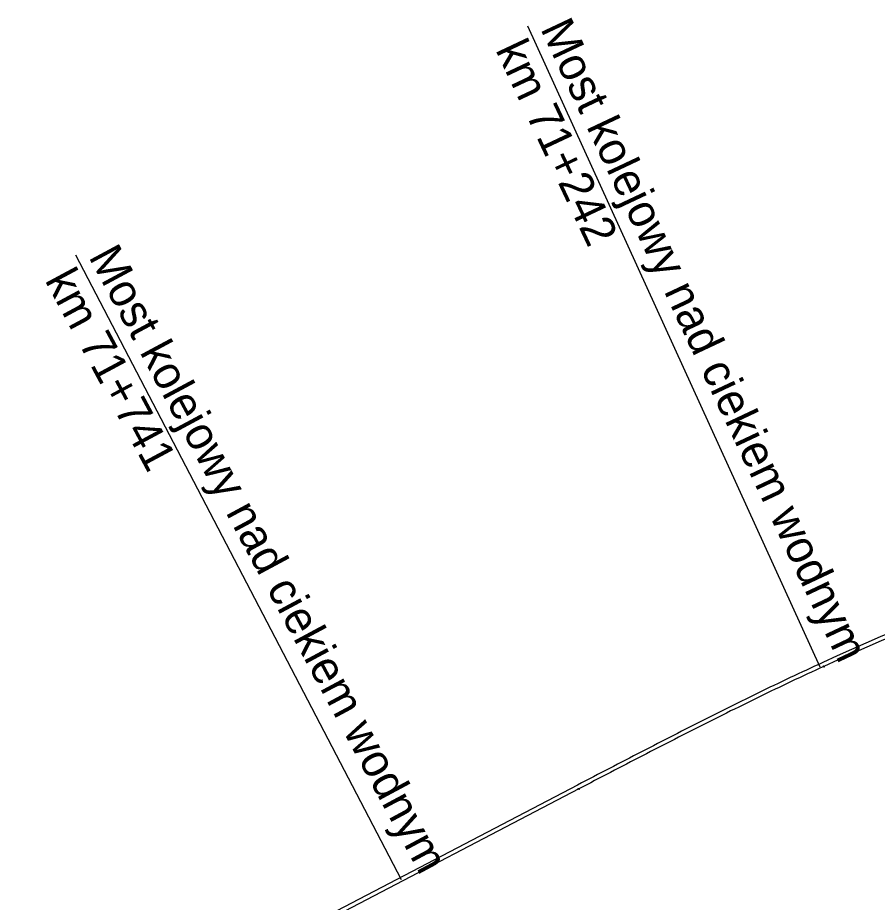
# Model space of a CAD drawing. Extents: x 6540591 to 6566579, y 5525343 to 5532423.
# Drawn here: x 6547196 to 6548106, y 5526559 to 5527495 of the extents above; entities that cross this region are included whole.
import ezdxf

# ---------------------------------------------------------------- set-up
doc = ezdxf.new("R2010")
doc.units = 0
for name, color, linetype in [('IR_ps_geometria', 7, 'Continuous'), ('TOR_PS_OPIS_T-opisy dodatkowe', 7, 'Continuous'), ('TOR_PS_T-tory projektowane', 7, 'Continuous')]:
    doc.layers.add(name, color=color, linetype=linetype)

msp = doc.modelspace()

# ---------------------------------------------------------------- linework, layer by layer
at = {"layer": 'IR_ps_geometria'}
for points in [[(6548049.46, 5526808.53), (6548049.56, 5526808.3), (6548049.59, 5526808.31), (6548049.62, 5526808.32), (6548049.66, 5526808.32), (6548049.69, 5526808.32), (6548049.72, 5526808.32), (6548049.75, 5526808.31), (6548049.78, 5526808.29), (6548049.81, 5526808.28), (6548049.84, 5526808.26), (6548049.86, 5526808.23), (6548049.88, 5526808.2), (6548049.89, 5526808.18), (6548049.9, 5526808.15), (6548049.91, 5526808.11), (6548049.91, 5526808.08), (6548049.91, 5526808.05), (6548049.91, 5526808.02), (6548049.9, 5526807.98), (6548049.89, 5526807.95), (6548049.87, 5526807.93), (6548049.85, 5526807.9), (6548049.82, 5526807.88), (6548049.8, 5526807.86), (6548049.77, 5526807.84), (6548049.74, 5526807.83), (6548049.71, 5526807.83), (6548049.67, 5526807.82), (6548049.64, 5526807.82), (6548049.61, 5526807.83), (6548049.58, 5526807.84), (6548049.55, 5526807.85), (6548049.52, 5526807.87), (6548049.49, 5526807.89), (6548049.47, 5526807.91), (6548049.45, 5526807.94), (6548049.44, 5526807.97), (6548049.43, 5526808), (6548049.42, 5526808.03), (6548049.42, 5526808.06), (6548049.42, 5526808.1), (6548049.42, 5526808.13), (6548049.43, 5526808.16), (6548049.44, 5526808.19), (6548049.46, 5526808.22), (6548049.48, 5526808.24), (6548049.51, 5526808.26), (6548049.53, 5526808.28), (6548049.56, 5526808.3), (6548049.35, 5526808.75), (6548049.32, 5526808.74), (6548049.29, 5526808.74), (6548049.26, 5526808.73), (6548049.23, 5526808.73), (6548049.19, 5526808.74), (6548049.16, 5526808.75), (6548049.13, 5526808.76), (6548049.1, 5526808.78), (6548049.08, 5526808.8), (6548049.06, 5526808.82), (6548049.04, 5526808.85), (6548049.02, 5526808.88), (6548049.01, 5526808.91), (6548049, 5526808.94), (6548049, 5526808.97), (6548049, 5526809.01), (6548049.01, 5526809.04), (6548049.01, 5526809.07), (6548049.03, 5526809.1), (6548049.05, 5526809.13), (6548049.07, 5526809.15), (6548049.09, 5526809.17), (6548049.12, 5526809.19), (6548049.15, 5526809.21), (6548049.18, 5526809.22), (6548049.21, 5526809.23), (6548049.24, 5526809.23), (6548049.27, 5526809.23), (6548049.31, 5526809.23), (6548049.34, 5526809.22), (6548049.37, 5526809.2), (6548049.39, 5526809.19), (6548049.42, 5526809.16), (6548049.44, 5526809.14), (6548049.46, 5526809.11), (6548049.48, 5526809.09), (6548049.49, 5526809.05), (6548049.5, 5526809.02), (6548049.5, 5526808.99), (6548049.5, 5526808.96), (6548049.49, 5526808.93), (6548049.48, 5526808.89), (6548049.47, 5526808.86), (6548049.45, 5526808.84), (6548049.43, 5526808.81), (6548049.41, 5526808.79), (6548049.38, 5526808.77), (6548049.35, 5526808.75)], [(6548049.46, 5526808.53), (6548049.56, 5526808.3), (6548049.59, 5526808.31), (6548049.62, 5526808.32), (6548049.66, 5526808.32), (6548049.69, 5526808.32), (6548049.72, 5526808.32), (6548049.75, 5526808.31), (6548049.78, 5526808.29), (6548049.81, 5526808.28), (6548049.84, 5526808.26), (6548049.86, 5526808.23), (6548049.88, 5526808.2), (6548049.89, 5526808.18), (6548049.9, 5526808.15), (6548049.91, 5526808.11), (6548049.91, 5526808.08), (6548049.91, 5526808.05), (6548049.91, 5526808.02), (6548049.9, 5526807.98), (6548049.89, 5526807.95), (6548049.87, 5526807.93), (6548049.85, 5526807.9), (6548049.82, 5526807.88), (6548049.8, 5526807.86), (6548049.77, 5526807.84), (6548049.74, 5526807.83), (6548049.71, 5526807.83), (6548049.67, 5526807.82), (6548049.64, 5526807.82), (6548049.61, 5526807.83), (6548049.58, 5526807.84), (6548049.55, 5526807.85), (6548049.52, 5526807.87), (6548049.49, 5526807.89), (6548049.47, 5526807.91), (6548049.45, 5526807.94), (6548049.44, 5526807.97), (6548049.43, 5526808), (6548049.42, 5526808.03), (6548049.42, 5526808.06), (6548049.42, 5526808.1), (6548049.42, 5526808.13), (6548049.43, 5526808.16), (6548049.44, 5526808.19), (6548049.46, 5526808.22), (6548049.48, 5526808.24), (6548049.51, 5526808.26), (6548049.53, 5526808.28), (6548049.56, 5526808.3), (6548049.35, 5526808.75), (6548049.32, 5526808.74), (6548049.29, 5526808.74), (6548049.26, 5526808.73), (6548049.23, 5526808.73), (6548049.19, 5526808.74), (6548049.16, 5526808.75), (6548049.13, 5526808.76), (6548049.1, 5526808.78), (6548049.08, 5526808.8), (6548049.06, 5526808.82), (6548049.04, 5526808.85), (6548049.02, 5526808.88), (6548049.01, 5526808.91), (6548049, 5526808.94), (6548049, 5526808.97), (6548049, 5526809.01), (6548049.01, 5526809.04), (6548049.01, 5526809.07), (6548049.03, 5526809.1), (6548049.05, 5526809.13), (6548049.07, 5526809.15), (6548049.09, 5526809.17), (6548049.12, 5526809.19), (6548049.15, 5526809.21), (6548049.18, 5526809.22), (6548049.21, 5526809.23), (6548049.24, 5526809.23), (6548049.27, 5526809.23), (6548049.31, 5526809.23), (6548049.34, 5526809.22), (6548049.37, 5526809.2), (6548049.39, 5526809.19), (6548049.42, 5526809.16), (6548049.44, 5526809.14), (6548049.46, 5526809.11), (6548049.48, 5526809.09), (6548049.49, 5526809.05), (6548049.5, 5526809.02), (6548049.5, 5526808.99), (6548049.5, 5526808.96), (6548049.49, 5526808.93), (6548049.48, 5526808.89), (6548049.47, 5526808.86), (6548049.45, 5526808.84), (6548049.43, 5526808.81), (6548049.41, 5526808.79), (6548049.38, 5526808.77), (6548049.35, 5526808.75)], [(6548049.46, 5526808.53), (6548049.56, 5526808.3), (6548049.59, 5526808.31), (6548049.62, 5526808.32), (6548049.66, 5526808.32), (6548049.69, 5526808.32), (6548049.72, 5526808.32), (6548049.75, 5526808.31), (6548049.78, 5526808.29), (6548049.81, 5526808.28), (6548049.84, 5526808.26), (6548049.86, 5526808.23), (6548049.88, 5526808.2), (6548049.89, 5526808.18), (6548049.9, 5526808.15), (6548049.91, 5526808.11), (6548049.91, 5526808.08), (6548049.91, 5526808.05), (6548049.91, 5526808.02), (6548049.9, 5526807.98), (6548049.89, 5526807.95), (6548049.87, 5526807.93), (6548049.85, 5526807.9), (6548049.82, 5526807.88), (6548049.8, 5526807.86), (6548049.77, 5526807.84), (6548049.74, 5526807.83), (6548049.71, 5526807.83), (6548049.67, 5526807.82), (6548049.64, 5526807.82), (6548049.61, 5526807.83), (6548049.58, 5526807.84), (6548049.55, 5526807.85), (6548049.52, 5526807.87), (6548049.49, 5526807.89), (6548049.47, 5526807.91), (6548049.45, 5526807.94), (6548049.44, 5526807.97), (6548049.43, 5526808), (6548049.42, 5526808.03), (6548049.42, 5526808.06), (6548049.42, 5526808.1), (6548049.42, 5526808.13), (6548049.43, 5526808.16), (6548049.44, 5526808.19), (6548049.46, 5526808.22), (6548049.48, 5526808.24), (6548049.51, 5526808.26), (6548049.53, 5526808.28), (6548049.56, 5526808.3), (6548049.35, 5526808.75), (6548049.32, 5526808.74), (6548049.29, 5526808.74), (6548049.26, 5526808.73), (6548049.23, 5526808.73), (6548049.19, 5526808.74), (6548049.16, 5526808.75), (6548049.13, 5526808.76), (6548049.1, 5526808.78), (6548049.08, 5526808.8), (6548049.06, 5526808.82), (6548049.04, 5526808.85), (6548049.02, 5526808.88), (6548049.01, 5526808.91), (6548049, 5526808.94), (6548049, 5526808.97), (6548049, 5526809.01), (6548049.01, 5526809.04), (6548049.01, 5526809.07), (6548049.03, 5526809.1), (6548049.05, 5526809.13), (6548049.07, 5526809.15), (6548049.09, 5526809.17), (6548049.12, 5526809.19), (6548049.15, 5526809.21), (6548049.18, 5526809.22), (6548049.21, 5526809.23), (6548049.24, 5526809.23), (6548049.27, 5526809.23), (6548049.31, 5526809.23), (6548049.34, 5526809.22), (6548049.37, 5526809.2), (6548049.39, 5526809.19), (6548049.42, 5526809.16), (6548049.44, 5526809.14), (6548049.46, 5526809.11), (6548049.48, 5526809.09), (6548049.49, 5526809.05), (6548049.5, 5526809.02), (6548049.5, 5526808.99), (6548049.5, 5526808.96), (6548049.49, 5526808.93), (6548049.48, 5526808.89), (6548049.47, 5526808.86), (6548049.45, 5526808.84), (6548049.43, 5526808.81), (6548049.41, 5526808.79), (6548049.38, 5526808.77), (6548049.35, 5526808.75)], [(6548049.46, 5526808.53), (6548049.56, 5526808.3), (6548049.59, 5526808.31), (6548049.62, 5526808.32), (6548049.66, 5526808.32), (6548049.69, 5526808.32), (6548049.72, 5526808.32), (6548049.75, 5526808.31), (6548049.78, 5526808.29), (6548049.81, 5526808.28), (6548049.84, 5526808.26), (6548049.86, 5526808.23), (6548049.88, 5526808.2), (6548049.89, 5526808.18), (6548049.9, 5526808.15), (6548049.91, 5526808.11), (6548049.91, 5526808.08), (6548049.91, 5526808.05), (6548049.91, 5526808.02), (6548049.9, 5526807.98), (6548049.89, 5526807.95), (6548049.87, 5526807.93), (6548049.85, 5526807.9), (6548049.82, 5526807.88), (6548049.8, 5526807.86), (6548049.77, 5526807.84), (6548049.74, 5526807.83), (6548049.71, 5526807.83), (6548049.67, 5526807.82), (6548049.64, 5526807.82), (6548049.61, 5526807.83), (6548049.58, 5526807.84), (6548049.55, 5526807.85), (6548049.52, 5526807.87), (6548049.49, 5526807.89), (6548049.47, 5526807.91), (6548049.45, 5526807.94), (6548049.44, 5526807.97), (6548049.43, 5526808), (6548049.42, 5526808.03), (6548049.42, 5526808.06), (6548049.42, 5526808.1), (6548049.42, 5526808.13), (6548049.43, 5526808.16), (6548049.44, 5526808.19), (6548049.46, 5526808.22), (6548049.48, 5526808.24), (6548049.51, 5526808.26), (6548049.53, 5526808.28), (6548049.56, 5526808.3), (6548049.35, 5526808.75), (6548049.32, 5526808.74), (6548049.29, 5526808.74), (6548049.26, 5526808.73), (6548049.23, 5526808.73), (6548049.19, 5526808.74), (6548049.16, 5526808.75), (6548049.13, 5526808.76), (6548049.1, 5526808.78), (6548049.08, 5526808.8), (6548049.06, 5526808.82), (6548049.04, 5526808.85), (6548049.02, 5526808.88), (6548049.01, 5526808.91), (6548049, 5526808.94), (6548049, 5526808.97), (6548049, 5526809.01), (6548049.01, 5526809.04), (6548049.01, 5526809.07), (6548049.03, 5526809.1), (6548049.05, 5526809.13), (6548049.07, 5526809.15), (6548049.09, 5526809.17), (6548049.12, 5526809.19), (6548049.15, 5526809.21), (6548049.18, 5526809.22), (6548049.21, 5526809.23), (6548049.24, 5526809.23), (6548049.27, 5526809.23), (6548049.31, 5526809.23), (6548049.34, 5526809.22), (6548049.37, 5526809.2), (6548049.39, 5526809.19), (6548049.42, 5526809.16), (6548049.44, 5526809.14), (6548049.46, 5526809.11), (6548049.48, 5526809.09), (6548049.49, 5526809.05), (6548049.5, 5526809.02), (6548049.5, 5526808.99), (6548049.5, 5526808.96), (6548049.49, 5526808.93), (6548049.48, 5526808.89), (6548049.47, 5526808.86), (6548049.45, 5526808.84), (6548049.43, 5526808.81), (6548049.41, 5526808.79), (6548049.38, 5526808.77), (6548049.35, 5526808.75)], [(6547790.06, 5526678.94), (6547790.17, 5526678.72), (6547790.2, 5526678.73), (6547790.24, 5526678.74), (6547790.27, 5526678.75), (6547790.3, 5526678.75), (6547790.33, 5526678.74), (6547790.37, 5526678.74), (6547790.4, 5526678.72), (6547790.42, 5526678.71), (6547790.45, 5526678.69), (6547790.47, 5526678.67), (6547790.5, 5526678.64), (6547790.51, 5526678.61), (6547790.53, 5526678.58), (6547790.53, 5526678.55), (6547790.54, 5526678.52), (6547790.54, 5526678.49), (6547790.54, 5526678.45), (6547790.53, 5526678.42), (6547790.52, 5526678.39), (6547790.5, 5526678.36), (6547790.48, 5526678.34), (6547790.46, 5526678.31), (6547790.43, 5526678.29), (6547790.41, 5526678.28), (6547790.38, 5526678.26), (6547790.34, 5526678.25), (6547790.31, 5526678.25), (6547790.28, 5526678.25), (6547790.25, 5526678.25), (6547790.22, 5526678.26), (6547790.18, 5526678.27), (6547790.16, 5526678.29), (6547790.13, 5526678.31), (6547790.11, 5526678.33), (6547790.09, 5526678.35), (6547790.07, 5526678.38), (6547790.06, 5526678.41), (6547790.05, 5526678.44), (6547790.04, 5526678.47), (6547790.04, 5526678.51), (6547790.04, 5526678.54), (6547790.05, 5526678.57), (6547790.06, 5526678.6), (6547790.08, 5526678.63), (6547790.1, 5526678.66), (6547790.12, 5526678.68), (6547790.15, 5526678.7), (6547790.17, 5526678.72), (6547789.94, 5526679.16), (6547789.91, 5526679.15), (6547789.88, 5526679.14), (6547789.85, 5526679.13), (6547789.82, 5526679.13), (6547789.78, 5526679.14), (6547789.75, 5526679.15), (6547789.72, 5526679.16), (6547789.69, 5526679.17), (6547789.67, 5526679.19), (6547789.64, 5526679.21), (6547789.62, 5526679.24), (6547789.61, 5526679.27), (6547789.59, 5526679.3), (6547789.58, 5526679.33), (6547789.58, 5526679.36), (6547789.58, 5526679.39), (6547789.58, 5526679.43), (6547789.59, 5526679.46), (6547789.6, 5526679.49), (6547789.62, 5526679.52), (6547789.64, 5526679.54), (6547789.66, 5526679.57), (6547789.68, 5526679.59), (6547789.71, 5526679.61), (6547789.74, 5526679.62), (6547789.77, 5526679.63), (6547789.81, 5526679.63), (6547789.84, 5526679.63), (6547789.87, 5526679.63), (6547789.9, 5526679.62), (6547789.93, 5526679.61), (6547789.96, 5526679.59), (6547789.99, 5526679.58), (6547790.01, 5526679.55), (6547790.03, 5526679.53), (6547790.05, 5526679.5), (6547790.06, 5526679.47), (6547790.07, 5526679.44), (6547790.08, 5526679.41), (6547790.08, 5526679.37), (6547790.07, 5526679.34), (6547790.07, 5526679.31), (6547790.05, 5526679.28), (6547790.04, 5526679.25), (6547790.02, 5526679.22), (6547790, 5526679.2), (6547789.97, 5526679.18), (6547789.94, 5526679.16)], [(6547790.06, 5526678.94), (6547790.17, 5526678.72), (6547790.2, 5526678.73), (6547790.24, 5526678.74), (6547790.27, 5526678.75), (6547790.3, 5526678.75), (6547790.33, 5526678.74), (6547790.37, 5526678.74), (6547790.4, 5526678.72), (6547790.42, 5526678.71), (6547790.45, 5526678.69), (6547790.47, 5526678.67), (6547790.5, 5526678.64), (6547790.51, 5526678.61), (6547790.53, 5526678.58), (6547790.53, 5526678.55), (6547790.54, 5526678.52), (6547790.54, 5526678.49), (6547790.54, 5526678.45), (6547790.53, 5526678.42), (6547790.52, 5526678.39), (6547790.5, 5526678.36), (6547790.48, 5526678.34), (6547790.46, 5526678.31), (6547790.43, 5526678.29), (6547790.41, 5526678.28), (6547790.38, 5526678.26), (6547790.34, 5526678.25), (6547790.31, 5526678.25), (6547790.28, 5526678.25), (6547790.25, 5526678.25), (6547790.22, 5526678.26), (6547790.18, 5526678.27), (6547790.16, 5526678.29), (6547790.13, 5526678.31), (6547790.11, 5526678.33), (6547790.09, 5526678.35), (6547790.07, 5526678.38), (6547790.06, 5526678.41), (6547790.05, 5526678.44), (6547790.04, 5526678.47), (6547790.04, 5526678.51), (6547790.04, 5526678.54), (6547790.05, 5526678.57), (6547790.06, 5526678.6), (6547790.08, 5526678.63), (6547790.1, 5526678.66), (6547790.12, 5526678.68), (6547790.15, 5526678.7), (6547790.17, 5526678.72), (6547789.94, 5526679.16), (6547789.91, 5526679.15), (6547789.88, 5526679.14), (6547789.85, 5526679.13), (6547789.82, 5526679.13), (6547789.78, 5526679.14), (6547789.75, 5526679.15), (6547789.72, 5526679.16), (6547789.69, 5526679.17), (6547789.67, 5526679.19), (6547789.64, 5526679.21), (6547789.62, 5526679.24), (6547789.61, 5526679.27), (6547789.59, 5526679.3), (6547789.58, 5526679.33), (6547789.58, 5526679.36), (6547789.58, 5526679.39), (6547789.58, 5526679.43), (6547789.59, 5526679.46), (6547789.6, 5526679.49), (6547789.62, 5526679.52), (6547789.64, 5526679.54), (6547789.66, 5526679.57), (6547789.68, 5526679.59), (6547789.71, 5526679.61), (6547789.74, 5526679.62), (6547789.77, 5526679.63), (6547789.81, 5526679.63), (6547789.84, 5526679.63), (6547789.87, 5526679.63), (6547789.9, 5526679.62), (6547789.93, 5526679.61), (6547789.96, 5526679.59), (6547789.99, 5526679.58), (6547790.01, 5526679.55), (6547790.03, 5526679.53), (6547790.05, 5526679.5), (6547790.06, 5526679.47), (6547790.07, 5526679.44), (6547790.08, 5526679.41), (6547790.08, 5526679.37), (6547790.07, 5526679.34), (6547790.07, 5526679.31), (6547790.05, 5526679.28), (6547790.04, 5526679.25), (6547790.02, 5526679.22), (6547790, 5526679.2), (6547789.97, 5526679.18), (6547789.94, 5526679.16)], [(6547790.06, 5526678.94), (6547790.17, 5526678.72), (6547790.2, 5526678.73), (6547790.24, 5526678.74), (6547790.27, 5526678.75), (6547790.3, 5526678.75), (6547790.33, 5526678.74), (6547790.37, 5526678.74), (6547790.4, 5526678.72), (6547790.42, 5526678.71), (6547790.45, 5526678.69), (6547790.47, 5526678.67), (6547790.5, 5526678.64), (6547790.51, 5526678.61), (6547790.53, 5526678.58), (6547790.53, 5526678.55), (6547790.54, 5526678.52), (6547790.54, 5526678.49), (6547790.54, 5526678.45), (6547790.53, 5526678.42), (6547790.52, 5526678.39), (6547790.5, 5526678.36), (6547790.48, 5526678.34), (6547790.46, 5526678.31), (6547790.43, 5526678.29), (6547790.41, 5526678.28), (6547790.38, 5526678.26), (6547790.34, 5526678.25), (6547790.31, 5526678.25), (6547790.28, 5526678.25), (6547790.25, 5526678.25), (6547790.22, 5526678.26), (6547790.18, 5526678.27), (6547790.16, 5526678.29), (6547790.13, 5526678.31), (6547790.11, 5526678.33), (6547790.09, 5526678.35), (6547790.07, 5526678.38), (6547790.06, 5526678.41), (6547790.05, 5526678.44), (6547790.04, 5526678.47), (6547790.04, 5526678.51), (6547790.04, 5526678.54), (6547790.05, 5526678.57), (6547790.06, 5526678.6), (6547790.08, 5526678.63), (6547790.1, 5526678.66), (6547790.12, 5526678.68), (6547790.15, 5526678.7), (6547790.17, 5526678.72), (6547789.94, 5526679.16), (6547789.91, 5526679.15), (6547789.88, 5526679.14), (6547789.85, 5526679.13), (6547789.82, 5526679.13), (6547789.78, 5526679.14), (6547789.75, 5526679.15), (6547789.72, 5526679.16), (6547789.69, 5526679.17), (6547789.67, 5526679.19), (6547789.64, 5526679.21), (6547789.62, 5526679.24), (6547789.61, 5526679.27), (6547789.59, 5526679.3), (6547789.58, 5526679.33), (6547789.58, 5526679.36), (6547789.58, 5526679.39), (6547789.58, 5526679.43), (6547789.59, 5526679.46), (6547789.6, 5526679.49), (6547789.62, 5526679.52), (6547789.64, 5526679.54), (6547789.66, 5526679.57), (6547789.68, 5526679.59), (6547789.71, 5526679.61), (6547789.74, 5526679.62), (6547789.77, 5526679.63), (6547789.81, 5526679.63), (6547789.84, 5526679.63), (6547789.87, 5526679.63), (6547789.9, 5526679.62), (6547789.93, 5526679.61), (6547789.96, 5526679.59), (6547789.99, 5526679.58), (6547790.01, 5526679.55), (6547790.03, 5526679.53), (6547790.05, 5526679.5), (6547790.06, 5526679.47), (6547790.07, 5526679.44), (6547790.08, 5526679.41), (6547790.08, 5526679.37), (6547790.07, 5526679.34), (6547790.07, 5526679.31), (6547790.05, 5526679.28), (6547790.04, 5526679.25), (6547790.02, 5526679.22), (6547790, 5526679.2), (6547789.97, 5526679.18), (6547789.94, 5526679.16)], [(6547790.06, 5526678.94), (6547790.17, 5526678.72), (6547790.2, 5526678.73), (6547790.24, 5526678.74), (6547790.27, 5526678.75), (6547790.3, 5526678.75), (6547790.33, 5526678.74), (6547790.37, 5526678.74), (6547790.4, 5526678.72), (6547790.42, 5526678.71), (6547790.45, 5526678.69), (6547790.47, 5526678.67), (6547790.5, 5526678.64), (6547790.51, 5526678.61), (6547790.53, 5526678.58), (6547790.53, 5526678.55), (6547790.54, 5526678.52), (6547790.54, 5526678.49), (6547790.54, 5526678.45), (6547790.53, 5526678.42), (6547790.52, 5526678.39), (6547790.5, 5526678.36), (6547790.48, 5526678.34), (6547790.46, 5526678.31), (6547790.43, 5526678.29), (6547790.41, 5526678.28), (6547790.38, 5526678.26), (6547790.34, 5526678.25), (6547790.31, 5526678.25), (6547790.28, 5526678.25), (6547790.25, 5526678.25), (6547790.22, 5526678.26), (6547790.18, 5526678.27), (6547790.16, 5526678.29), (6547790.13, 5526678.31), (6547790.11, 5526678.33), (6547790.09, 5526678.35), (6547790.07, 5526678.38), (6547790.06, 5526678.41), (6547790.05, 5526678.44), (6547790.04, 5526678.47), (6547790.04, 5526678.51), (6547790.04, 5526678.54), (6547790.05, 5526678.57), (6547790.06, 5526678.6), (6547790.08, 5526678.63), (6547790.1, 5526678.66), (6547790.12, 5526678.68), (6547790.15, 5526678.7), (6547790.17, 5526678.72), (6547789.94, 5526679.16), (6547789.91, 5526679.15), (6547789.88, 5526679.14), (6547789.85, 5526679.13), (6547789.82, 5526679.13), (6547789.78, 5526679.14), (6547789.75, 5526679.15), (6547789.72, 5526679.16), (6547789.69, 5526679.17), (6547789.67, 5526679.19), (6547789.64, 5526679.21), (6547789.62, 5526679.24), (6547789.61, 5526679.27), (6547789.59, 5526679.3), (6547789.58, 5526679.33), (6547789.58, 5526679.36), (6547789.58, 5526679.39), (6547789.58, 5526679.43), (6547789.59, 5526679.46), (6547789.6, 5526679.49), (6547789.62, 5526679.52), (6547789.64, 5526679.54), (6547789.66, 5526679.57), (6547789.68, 5526679.59), (6547789.71, 5526679.61), (6547789.74, 5526679.62), (6547789.77, 5526679.63), (6547789.81, 5526679.63), (6547789.84, 5526679.63), (6547789.87, 5526679.63), (6547789.9, 5526679.62), (6547789.93, 5526679.61), (6547789.96, 5526679.59), (6547789.99, 5526679.58), (6547790.01, 5526679.55), (6547790.03, 5526679.53), (6547790.05, 5526679.5), (6547790.06, 5526679.47), (6547790.07, 5526679.44), (6547790.08, 5526679.41), (6547790.08, 5526679.37), (6547790.07, 5526679.34), (6547790.07, 5526679.31), (6547790.05, 5526679.28), (6547790.04, 5526679.25), (6547790.02, 5526679.22), (6547790, 5526679.2), (6547789.97, 5526679.18), (6547789.94, 5526679.16)]]:
    msp.add_lwpolyline(points, close=True, dxfattribs=at)
at = {"layer": 'TOR_PS_OPIS_T-opisy dodatkowe'}
for p, q in [((6547735.94, 5527485.84), (6548045.21, 5526808.07)), ((6547257.63, 5527243.94), (6547602.02, 5526583.33))]:
    msp.add_line(p, q, dxfattribs=at)
at = {"layer": 'TOR_PS_T-tory projektowane'}
for p, q in [((6547790.06, 5526678.94), (6546521.11, 5526017.4)), ((6547788.93, 5526683.09), (6546521.48, 5526022.34))]:
    msp.add_line(p, q, dxfattribs=at)
for points in [[(6548048.33, 5526812.68), (6548044.01, 5526810.7), (6548039.69, 5526808.72), (6548035.37, 5526806.72), (6548031.06, 5526804.72), (6548026.75, 5526802.71), (6548022.44, 5526800.7), (6548018.14, 5526798.67), (6548013.84, 5526796.64), (6548009.55, 5526794.61), (6548005.25, 5526792.57), (6548000.96, 5526790.52), (6547996.67, 5526788.47), (6547992.39, 5526786.41), (6547988.11, 5526784.35), (6547983.83, 5526782.28), (6547979.55, 5526780.2), (6547975.27, 5526778.12), (6547971, 5526776.03), (6547966.73, 5526773.94), (6547962.47, 5526771.85), (6547958.2, 5526769.74), (6547953.94, 5526767.64), (6547949.68, 5526765.53), (6547945.42, 5526763.41), (6547941.17, 5526761.29), (6547936.91, 5526759.17), (6547932.66, 5526757.04), (6547928.41, 5526754.91), (6547924.16, 5526752.78), (6547919.92, 5526750.64), (6547915.68, 5526748.49), (6547911.43, 5526746.35), (6547907.19, 5526744.2), (6547902.95, 5526742.04), (6547898.72, 5526739.89), (6547894.48, 5526737.73), (6547890.25, 5526735.56), (6547886.02, 5526733.4), (6547881.79, 5526731.23), (6547877.56, 5526729.06), (6547873.33, 5526726.89), (6547869.1, 5526724.71), (6547864.87, 5526722.53), (6547860.65, 5526720.36), (6547856.43, 5526718.17), (6547852.2, 5526715.99), (6547847.98, 5526713.8), (6547843.76, 5526711.62), (6547839.54, 5526709.43), (6547835.32, 5526707.24), (6547831.1, 5526705.05), (6547826.88, 5526702.86), (6547822.66, 5526700.66), (6547818.45, 5526698.47), (6547814.23, 5526696.27), (6547810.01, 5526694.08), (6547805.8, 5526691.88), (6547801.58, 5526689.68), (6547797.36, 5526687.49), (6547793.15, 5526685.29), (6547788.93, 5526683.09)], [(6548049.46, 5526808.53), (6548045.14, 5526806.55), (6548040.82, 5526804.56), (6548036.5, 5526802.56), (6548032.19, 5526800.56), (6548027.88, 5526798.55), (6548023.57, 5526796.54), (6548019.27, 5526794.52), (6548014.97, 5526792.49), (6548010.67, 5526790.46), (6548006.38, 5526788.42), (6548002.09, 5526786.37), (6547997.8, 5526784.32), (6547993.52, 5526782.26), (6547989.23, 5526780.19), (6547984.95, 5526778.12), (6547980.68, 5526776.05), (6547976.4, 5526773.97), (6547972.13, 5526771.88), (6547967.86, 5526769.79), (6547963.59, 5526767.69), (6547959.33, 5526765.59), (6547955.07, 5526763.49), (6547950.81, 5526761.38), (6547946.55, 5526759.26), (6547942.29, 5526757.14), (6547938.04, 5526755.02), (6547933.79, 5526752.89), (6547929.54, 5526750.76), (6547925.29, 5526748.62), (6547921.04, 5526746.49), (6547916.8, 5526744.34), (6547912.56, 5526742.2), (6547908.32, 5526740.05), (6547904.08, 5526737.89), (6547899.84, 5526735.74), (6547895.61, 5526733.58), (6547891.37, 5526731.41), (6547887.14, 5526729.25), (6547882.91, 5526727.08), (6547878.68, 5526724.91), (6547874.45, 5526722.74), (6547870.23, 5526720.56), (6547866, 5526718.38), (6547861.77, 5526716.21), (6547857.55, 5526714.02), (6547853.33, 5526711.84), (6547849.11, 5526709.65), (6547844.88, 5526707.47), (6547840.66, 5526705.28), (6547836.44, 5526703.09), (6547832.23, 5526700.9), (6547828.01, 5526698.71), (6547823.79, 5526696.51), (6547819.57, 5526694.32), (6547815.36, 5526692.12), (6547811.14, 5526689.93), (6547806.92, 5526687.73), (6547802.71, 5526685.53), (6547798.49, 5526683.34), (6547794.27, 5526681.14), (6547790.06, 5526678.94)]]:
    msp.add_lwpolyline(points, dxfattribs=at)
for centre, radius, start, end in [((6549214.77, 5524261.71), 2805, 103.69505, 114.57239), ((6549213.58, 5524262), 2800, 103.70034, 114.5671)]:
    msp.add_arc(centre, radius, start, end, dxfattribs=at)

# ---------------------------------------------------------------- texts
at = {"layer": 'TOR_PS_OPIS_T-opisy dodatkowe'}
for s, rotation, p in [('Most kolejowy nad ciekiem wodnym', 295.22707, (6547749.07, 5527483.12)), ('km 71+242', 295.22707, (6547701.58, 5527460.74)), ('Most kolejowy nad ciekiem wodnym', 298.23405, (6547270.89, 5527241.91)), ('km 71+741', 298.23405, (6547224.63, 5527217.07))]:
    msp.add_text(s, height=35, rotation=rotation, dxfattribs=at).set_placement(p)

doc.saveas('drawing.dxf')
